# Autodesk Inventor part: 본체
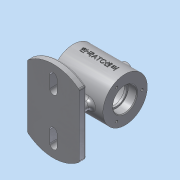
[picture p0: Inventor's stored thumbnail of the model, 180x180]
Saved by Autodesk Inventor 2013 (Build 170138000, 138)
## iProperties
Created: 2017-12
Part Number: 본체
Material: 알루미늄 6061
Document SubType Name: Modeling
Designer: dgall
Density: 2.71 g/cm^3
Mass: 467.692 g
Surface Area: 486.473 cm^2
Volume: 172.58 cm^3
Author: dgall
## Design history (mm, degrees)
sketch "스케치1"
  geometry: L1 (0, 0)-(70, 0); L2 (12, 16)-(0, 16); L3 (0, 16)-(0, 30); L4 (0, 30)-(70, 30); L5 (70, 30)-(70, 16); L6 (70, 16)-(58, 16); L7 (58, 16)-(58, 14); L8 (58, 14)-(55, 14); L9 (55, 14)-(55, 25); L10 (55, 25)-(15, 25); L11 (15, 25)-(15, 14); L12 (15, 14)-(12, 14); L13 (12, 16)-(12, 14)
  constraints: 26 end point, 9 parallel, 2 perpendicular, 2 vertical alignment, 1 collinear, 1 horizontal
  dimensions: "d0" = 70 distance of L3.end L4.end; "d2" = 60 diameter of L4 L1; "d3" = 32 diameter of L2 L1; "d4" = 28 diameter of L12 L1; "d5" = 50 diameter of L10 L1; "d6" = 28 diameter of L8 L1; "d7" = 32 diameter of L6 L1; "d8" = 12 distance of L2.start L2.end; "d9" = 12 distance of L5.end L6.end; "d10" = 40 distance of L9.end L10.end; "d11" = 3 distance of L11.end L12.end
revolve "회전1" sketch "스케치1" stored, may be unused: angle "d12" = 90 deg
node "작업 평면1"
sketch "스케치2"
  geometry: L1 (0, 30)-(0, -30) reference; C1 r 8 at (-35, 0); 1 further point
  constraints: 1 centre point, 1 horizontal alignment
  dimensions: "d14" = 16 diameter of C1; "d15" = 35 distance from line of L1 C1.centre
extrude "돌출1" join sketch "스케치2" stored distance "d16" = 10; taper "d17" = 0 deg
hole "구멍1" diameter "d20" = 8; stored, may be unused: countersink angle "d24" = 90 deg, drill point angle "d26" = 118 deg; dims "d18" = 10, "d19" = 10, "d21" = 6, "d22" = 4, "d23" = 2, "d25" = 8
sketch "스케치3"
  geometry: C1 r 30 at (0, 0) reference; 1 further point
  constraints: 1 vertical alignment
  dimensions: "d27" = 23 distance of C1.centre point (0, 23)
hole "구멍2" sketch "스케치3" at (0, 23) diameter "d28" = 3.242; stored, may be unused: countersink angle "d32" = 90 deg, drill point angle "d34" = 118 deg; dims "d29" = 8, "d30" = 4, "d31" = 2, "d33" = 10
sketch "스케치4"
  geometry: C1 r 16 at (0, 0) reference; 1 further point
  constraints: 1 vertical alignment
  dimensions: "d38" = 23 distance of C1.centre point (0, 23)
hole "구멍3" sketch "스케치4" at (0, 23) diameter "d39" = 3.242; stored, may be unused: countersink angle "d43" = 90 deg, drill point angle "d45" = 118 deg; dims "d40" = 8, "d41" = 4, "d42" = 2, "d44" = 10
node "작업 평면2"
sketch "스케치5"
  geometry: L1 (0, 30)-(0, -30) reference; L2 (-70, -42.426)-(-70, 42.426); L3 (0, -42.426)-(0, 42.426); L4 (-40, -24)-(-40, -40); L5 (-30, -40)-(-30, -24); L6 (-30, 24)-(-30, 40); L7 (-40, 40)-(-40, 24); A1 r 55 centre (-35, 0) between (-70, -42.426) and (-70, 42.426); A2 r 55 centre (-35, 0) between (-70, -42.426) and (0, -42.426); A3 r 55 centre (-35, 0) between (0, 42.426) and (-70, 42.426); A4 r 5 centre (-35, -40) between (-40, -40) and (-30, -40); A5 r 5 centre (-35, -24) between (-30, -24) and (-40, -24); A6 r 5 centre (-35, 40) between (-30, 40) and (-40, 40); A7 r 5 centre (-35, 24) between (-40, 24) and (-30, 24); 1 further point
  constraints: 16 point on circle, 13 end point, 8 tangent, 7 centre point, 4 parallel, 3 vertical alignment, 2 collinear, 2 concentric, 1 horizontal alignment
  dimensions: "d50" = 110 diameter of A1; "d52" = 35 distance from line of L1 A1.centre; "d53" = 70 distance between parallel lines of L3 L2; "d54" = 5 radius of A4; "d55" = 5 radius of A7; "d56" = 16 distance of A5.centre A4.centre; "d57" = 16 distance of A6.centre A7.centre; "d58" = 24 distance of A1.centre A5.centre; "d59" = 24 distance of A1.centre A7.centre
extrude "돌출2" join sketch "스케치5" distance "d60" = 10; taper "d61" = 0 deg
sketch "스케치6"
  geometry: L1 (0, 42.426)-(0, -42.426) reference; L2 (20, 5)-(50, 5); L3 (50, -5)-(20, -5); A1 r 5 centre (35, 24) between (30, 24) and (40, 24) reference; A2 r 55 centre (35, 0) between (0, -42.426) and (70, -42.426) reference; A3 r 5 centre (50, 0) between (50, -5) and (50, 5); A4 r 5 centre (20, 0) between (20, 5) and (20, -5); 2 further points
  constraints: 4 end point, 4 point on circle, 4 tangent, 2 centre point, 1 horizontal alignment, 1 midpoint, 1 parallel, 1 perpendicular, 1 vertical alignment
  dimensions: "d62" = 5 radius of A3; "d64" = 30 distance of A3.centre A4.centre
extrude "돌출3" join sketch "스케치6" stored distance "d65" = 10; taper "d66" = 0 deg
node "작업 평면3"
sketch "스케치7"
  geometry: L1 (-35, 30)-(35, 30) reference; 2 further points
  constraints: 1 horizontal alignment, 1 other
  dimensions: "d67" = 35 distance of point (0, 0) point (-35, 0)
feature "엠보싱1" sketch "스케치7" dims "d68" = 0.5, "d69" = 0
chamfer "모따기1" distance "d70" = 1; stored, may be unused: second distance "d71" = 2, angle "d72" = 45 deg
fillet "모깎기1" dims "d73" = 0.3
fillet "모깎기2" dims "d74" = 3
fillet "모깎기3" dims "d75" = 3
fillet "모깎기4" dims "d76" = 3
fillet "모깎기5" dims "d77" = 5
fillet "모깎기6" dims "d78" = 3
node "솔리드1"
pattern_circular "원형 패턴1" dims angle "d36" = 360 deg
pattern_circular "원형 패턴2" dims angle "d47" = 360 deg
other parameters: "d13" = 37, "d49" = -62
